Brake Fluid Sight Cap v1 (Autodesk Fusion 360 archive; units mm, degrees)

design "Brake Fluid Sight Cap" references "M4 Mitee Bite", "OP2", "Broached Hexagon Socket Head Cap Screw ANSI B18.3.1M - M4x0.7 x 6 Steel Grade 2 Plain", "Plain Washer ANSI B18.22M - 4 N Steel 100 HV Plain", "Broached Hexagon Socket Head Cap Screw ANSI B18.3.1M - M5x0.8 x 20 Steel Grade 2 Plain", "T-Slot Fence", "Coast Runner CR-1"
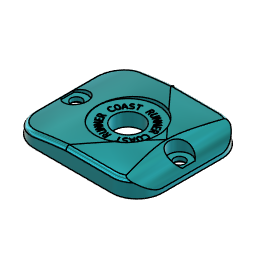
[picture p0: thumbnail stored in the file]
sketch "Sketch1" plane through (0, 0, 0) normal (0, 1, 0) x axis (1, 0, 0)
  line L1 (-22.86, 0) -> (-7.112, 0)
  line L2 (22.86, 0) -> (7.112, 0)
  line L3 (-19.05, 27.305) -> (19.05, 27.305)
  line L4 (-31.75, -14.605) -> (-31.75, 14.605)
  line L5 (19.05, -27.305) -> (-19.05, -27.305)
  line L6 (31.75, 14.605) -> (31.75, -14.605)
  line L7 (-31.75, -27.305) -> (31.75, 27.305)
  line L8 (31.75, -27.305) -> (-31.75, 27.305)
  circle C1 centre (0, 0) radius 7.112
  circle C2 centre (-25.527, 0) radius 2.667
  circle C3 centre (25.527, 0) radius 2.667
  arc A1 centre (19.05, 14.605) radius 12.7 clockwise from (19.05, 27.305) to (31.75, 14.605)
  arc A2 centre (19.05, -14.605) radius 12.7 clockwise from (31.75, -14.605) to (19.05, -27.305)
  arc A3 centre (-19.05, 14.605) radius 12.7 clockwise from (-31.75, 14.605) to (-19.05, 27.305)
  arc A4 centre (-19.05, -14.605) radius 12.7 clockwise from (-19.05, -27.305) to (-31.75, -14.605)
  point P1 (0, 0)
  point P2 (0, 0)
  point P3 (-7.112, 0)
  point P4 (-22.86, 0)
  point P6 (7.112, 0)
  point P7 (22.86, 0)
  point P13 (0, 0)
  point P9 (31.75, 27.305)
  point P12 (31.75, -27.305)
  point P10 (-31.75, 27.305)
  point P11 (-31.75, -27.305)
  coincident P1 P2
  coincident C1 P3
  horizontal L1
  coincident P4 C2
  coincident C1 P6
  horizontal L2
  coincident P7 C3
  horizontal L3
  perpendicular L3 L4
  parallel L3 L5
  parallel L4 L6
  coincident L7 P13
  coincident L8 P13
  coincident P2 P13
  coincident P9 L3
  coincident P9 L6
  tangent L3 A1
  tangent L6 A1
  coincident P12 L6
  coincident P12 L5
  tangent L6 A2
  tangent L5 A2
  coincident P10 L3
  coincident P10 L4
  tangent L3 A3
  tangent L4 A3
  coincident P11 L4
  coincident P11 L5
  tangent L4 A4
  tangent L5 A4
  dimension "d1" diameter C1 = 14.224
  dimension "d2" distance P3 P4 = 15.748
  dimension "d3" diameter C2 = 5.334
  dimension "d4" distance P6 P7 = 15.748
  dimension "d5" diameter C3 = 5.334
  dimension "d6" distance P11 P12 = 63.5
  dimension "d7" distance P10 P11 = 54.61
  dimension "d8" radius A1 = 12.7
  dimension "d9" radius A2 = 12.7
  dimension "d10" radius A3 = 12.7
  dimension "d11" radius A4 = 12.7
work_plane "WorkPlane1" sketch "Sketch1" AlongDistance 9.144
sketch "Sketch2" plane through (0, 9.144, 0) normal (0, 1, 0) x axis (1, 0, 0)
  line L1 (-31.75, -14.605) -> (-31.75, 14.605)
  line L2 (-19.05, 27.305) -> (19.05, 27.305)
  line L3 (31.75, 14.605) -> (31.75, -14.605)
  line L4 (19.05, -27.305) -> (-19.05, -27.305)
  line L5 (19.05, -26.67) -> (-19.05, -26.67)
  line L6 (31.115, 14.605) -> (31.115, -14.605)
  line L7 (-19.05, 26.67) -> (19.05, 26.67)
  line L8 (-31.115, -14.605) -> (-31.115, 14.605)
  line L9 (29.972, 0) -> (28.194, 0)
  line L10 (-29.972, 0) -> (-28.194, 0)
  line L11 (-29.972, 3.1725) -> (-29.972, 0)
  line L12 (-29.972, -3.1725) -> (-29.972, 0)
  line L13 (29.972, 3.1725) -> (29.972, 0)
  line L14 (29.972, -3.1725) -> (29.972, 0)
  arc A1 centre (-19.05, 14.605) radius 12.7 clockwise from (-31.75, 14.605) to (-19.05, 27.305)
  arc A2 centre (19.05, 14.605) radius 12.7 clockwise from (19.05, 27.305) to (31.75, 14.605)
  arc A3 centre (19.05, -14.605) radius 12.7 clockwise from (31.75, -14.605) to (19.05, -27.305)
  arc A4 centre (-19.05, -14.605) radius 12.7 clockwise from (-19.05, -27.305) to (-31.75, -14.605)
  arc A5 centre (-19.05, -14.605) radius 12.065 clockwise from (-19.05, -26.67) to (-31.115, -14.605)
  arc A6 centre (19.05, -14.605) radius 12.065 clockwise from (31.115, -14.605) to (19.05, -26.67)
  arc A7 centre (19.05, 14.605) radius 12.065 clockwise from (19.05, 26.67) to (31.115, 14.605)
  arc A8 centre (-19.05, 14.605) radius 12.065 clockwise from (-31.115, 14.605) to (-19.05, 26.67)
  circle C1 centre (-25.527, 0) radius 2.667
  circle C2 centre (0, 0) radius 7.112
  circle C3 centre (25.527, 0) radius 2.667
  circle C4 centre (-25.527, 0) radius 5.461
  circle C5 centre (25.527, 0) radius 5.461
  circle C6 centre (0, 0) radius 14.986
  point P29 (28.194, 0)
  point P31 (-28.194, 0)
  point P35 (-29.972, 3.1725)
  point P36 (-29.972, -3.1725)
  point P37 (29.972, 3.1725)
  point P38 (29.972, -3.1725)
  point P30 (29.972, 0)
  point P32 (-29.972, 0)
  coincident C3 P29
  perpendicular L6 L9
  coincident C1 P31
  horizontal L10
  concentric C1 C4
  concentric C3 C5
  coincident C4 P35
  perpendicular L10 L11
  coincident C4 P36
  perpendicular L10 L12
  coincident C5 P37
  perpendicular L9 L13
  coincident C5 P38
  perpendicular L9 L14
  concentric C2 C6
  dimension "d13" = -0.635
  dimension "d42" distance P29 P30 = 1.778
  dimension "d43" distance P31 P32 = 1.778
  dimension "d44" diameter C4 = 10.922
  dimension "d45" diameter C5 = 10.922
  dimension "d46" diameter C6 = 29.972
loft "Loft1" sketch "Sketch1" + "Sketch2"
sketch "Sketch3" plane through (0, 0, 0) normal (1, 0, 0) x axis (0, 0, -1)
  line L1 (26.67, 9.144) -> (-26.67, 9.144)
  line L2 (27.305, 0) -> (-27.305, 0)
  line L3 (0, 9.144) -> (0, 0)
  line L4 (0, 7.874) -> (0, 9.144)
  line L5 (-28.702, 7.874) -> (0, 7.874)
  line L6 (-26.67, 9.144) -> (-27.178, 7.874)
  line L7 (0, 9.144) -> (0, 7.874)
  line L8 (26.67, 9.144) -> (27.178, 7.874)
  arc A1 centre (0, -282.2956) radius 291.4396 clockwise from (-27.178, 7.874) to (0, 9.144)
  arc A2 centre (0, -282.2956) radius 291.4396 clockwise from (0, 9.144) to (27.178, 7.874)
  point P1 (0, 0)
  point P6 (0, 0)
  point P7 (0, 9.144)
  point P8 (0, 7.874)
  point P10 (-27.178, 7.874)
  point P2 (-26.67, 9.144)
  point P12 (-26.67, 9.144)
  point P16 (0, 9.144)
  point P13 (27.178, 7.874)
  point P14 (26.67, 9.144)
  coincident P1 P6
  midpoint L1 P7
  coincident L3 P8
  perpendicular L4 L5
  tangent L1 A1
  coincident L5 P10
  coincident P2 P12
  symmetric P7 L3 P16
  symmetric L3 P10 P13
  symmetric L3 A1 A2
  symmetric L3 P12 P14
  dimension "d14" distance P7 P8 = 1.27
sketch "Sketch4" plane through (0, 0, 0) normal (0, 0, 1) x axis (1, 0, 0)
  line L1 (-31.75, 3.81) -> (-31.75, 0)
  line L2 (41.4602, 3.81) -> (-31.75, 3.81)
  line L3 (19.05, 3.81) -> (-31.75, 3.81)
  line L4 (31.115, 9.144) -> (-31.115, 9.144)
  line L5 (19.05, 9.144) -> (19.05, 3.81)
  line L6 (-31.75, 3.81) -> (-31.115, 9.144)
  line L7 (19.05, 9.144) -> (-31.115, 9.144)
  line L8 (31.75, 1.778) -> (31.75, 0)
  line L9 (31.115, 9.144) -> (31.75, 1.778)
  line L10 (19.05, 9.144) -> (31.115, 9.144)
  arc A1 centre (19.05, -235.4278) radius 244.5718 clockwise from (-31.75, 3.81) to (19.05, 9.144)
  arc A2 centre (17.1186, -8.8173) radius 18.0649 clockwise from (19.05, 9.144) to (31.75, 1.778)
  point P5 (19.05, 3.81)
  point P8 (19.05, 9.144)
  point P6 (-31.115, 9.144)
  point P10 (-31.115, 9.144)
  point P7 (31.115, 9.144)
  point P14 (31.115, 9.144)
  point P15 (31.115, 9.144)
  point P2 (-31.75, 0)
  point P3 (-31.75, 3.81)
  point P11 (31.75, 0)
  point P12 (31.75, 1.778)
  vertical L1
  perpendicular L1 L2
  coincident L2 P5
  coincident L4 P8
  perpendicular L4 L5
  tangent L4 A1
  coincident P6 P10
  vertical L8
  coincident P7 P14
  coincident P7 P15
  dimension "d15" distance P2 P3 = 3.81
  dimension "d16" distance P3 P5 = 50.8
  dimension "d17" distance P11 P12 = 1.778
extrude "Extrude1" cut sketch "Sketch4" profile of A1 L6 L7 A2 L9 L10 distance 58.42
extrude "Extrude2" cut sketch "Sketch3" profile of L1 A1 L6 L8 A2 distance 52.07
extrude "Extrude3" cut sketch "Sketch1" profile of C1 C2 C3 along normal blind 39.37
sketch "Sketch5" plane through (0, 0, 0) normal (0, -1, 0) x axis (1, 0, 0)
  curve K1 (-31.75, 14.605) -> (-31.75, 14.605)
  curve K2 (-31.75, 14.605) -> (-31.75, 14.605)
  circle C1 centre (-25.527, 0) radius 2.667
  circle C2 centre (0, 0) radius 7.112
  circle C3 centre (25.527, 0) radius 2.667
  circle C4 centre (25.527, 0) radius 6.35
  circle C5 centre (-25.527, 0) radius 6.35
  circle C6 centre (0, 0) radius 9.779
  concentric C3 C4
  concentric C1 C5
  concentric C2 C6
  dimension "d24" = 3.556
  dimension "d25" diameter C4 = 12.7
  dimension "d26" diameter C5 = 12.7
  dimension "d27" diameter C6 = 19.558
extrude "Extrude4" cut sketch "Sketch5" profile of C4 C5 C6 against normal blind 3.556
fillet "Fillet1" radius 1.905
sketch "Sketch6" plane through (0, 0, 0) normal (0, -1, 0) x axis (1, 0, 0)
  curve K1 (-31.75, 14.605) -> (-31.75, 14.605)
  curve K2 (-28.194, -5.7628) -> (28.194, -5.7628)
  line L1 (-28.194, 14.605) -> (-28.194, 5.7628)
  curve K3 (28.194, 5.7628) -> (-28.194, 14.605)
  line L2 (-31.75, -27.2198) -> (-31.75, 0)
  line L3 (-15.2401, -23.749) -> (-31.75, -23.6999)
  line L4 (-13.4621, -23.749) -> (-15.2401, -23.749)
  line L5 (-13.4621, -28.9225) -> (-13.4621, -23.749)
  line L6 (-15.2401, -28.9225) -> (-13.4621, -28.9225)
  line L7 (-15.2401, -23.749) -> (-15.2401, -28.9225)
  line L8 (31.75, 36.9995) -> (31.75, -0.077)
  line L9 (31.75, 27.305) -> (15.24, 27.305)
  line L10 (13.462, 27.305) -> (15.24, 27.305)
  line L11 (13.462, 22.4524) -> (13.462, 27.305)
  line L12 (15.24, 22.4524) -> (13.462, 22.4524)
  line L13 (15.24, 27.305) -> (15.24, 22.4524)
  circle C1 centre (25.527, 0) radius 2.667
  circle C2 centre (-25.527, 0) radius 2.667
  arc A1 centre (25.527, 0) radius 6.35 clockwise from (28.194, -5.7628) to (28.194, 5.7628)
  arc A2 centre (-25.527, 0) radius 6.35 clockwise from (-28.194, 5.7628) to (-28.194, -5.7628)
  circle C3 centre (-25.527, 0) radius 4.064
  circle C4 centre (25.527, 0) radius 4.064
  point P13 (-31.75, 0)
  point P15 (-31.75, -23.6999)
  point P16 (-15.2401, -23.749)
  point P20 (31.75, -0.077)
  point P22 (15.24, 27.305)
  point P23 (31.75, 27.305)
  point P17 (-13.4621, -23.749)
  point P24 (13.462, 27.305)
  concentric C2 C3
  concentric C1 C4
  coincident K1 P13
  vertical L2
  coincident L2 P15
  coincident K2 P16
  horizontal L4
  vertical L5
  horizontal L6
  vertical L7
  coincident K1 P20
  vertical L8
  coincident K1 P22
  coincident L8 P23
  perpendicular L8 L9
  horizontal L10
  vertical L11
  horizontal L12
  vertical L13
  dimension "d32" diameter C3 = 8.128
  dimension "d33" diameter C4 = 8.128
  dimension "d34" distance P15 P16 = 16.51
  dimension "d35" distance P16 P17 = 1.778
  dimension "d36" distance P22 P23 = 16.51
  dimension "d37" distance P22 P24 = 1.778
extrude "Extrude5" cut sketch "Sketch6" profile of K1 K2 K3 L4 L5 L7 L10 L11 L13 against normal blind 0.762
extrude "Extrude6" cut sketch "Sketch6" profile of C1 C2 C3 C4 against normal blind 1.27
extrude "Extrude7" cut sketch "Sketch2" profile of C2 C6 against normal blind 2.54
fillet "Fillet2" radius 0.635
extrude "Extrude8" cut sketch "Sketch2" profile of C1 C3 C4 C5 L11 L12 L13 L14 against normal blind 5.842
fillet "Fillet3" radius 0.508
chamfer "Chamfer1" distance 1.27
sketch "Sketch1" plane through (0, 0, 0) normal (0, -1, 0) x axis (1, 0, 0)
  line L1 (-34.925, 28.575) -> (34.925, 28.575)
  line L2 (-34.925, -28.575) -> (-34.925, 28.575)
  line L3 (34.925, -28.575) -> (-34.925, -28.575)
  line L4 (34.925, 28.575) -> (34.925, -28.575)
  line L5 (-34.925, -28.575) -> (34.925, 28.575)
  line L6 (34.925, -28.575) -> (-34.925, 28.575)
  circle C1 centre (0, 0) radius 9.779
  circle C2 centre (0, 0) radius 7.112
  point P7 (0, 0)
  point P2 (0, 0)
  point P5 (-34.925, -28.575)
  point P6 (34.925, -28.575)
  point P4 (-34.925, 28.575)
  horizontal L1
  perpendicular L1 L2
  parallel L1 L3
  parallel L2 L4
  coincident L5 P7
  coincident L6 P7
  coincident P2 P7
  dimension "d56" distance P5 P6 = 69.85
  dimension "d57" distance P4 P5 = 57.15
extrude "Extrude1" new body sketch "Sketch1" profile of C1 C2 L1 L2 L3 L4 against normal blind 12.7
base_feature "Base Feature1"
copy_paste "CutPaste2"
component_from_bodies "Body->Comp"
base_feature "Base Feature1"
delete_face "DeleteFace1"
delete_face "DeleteFace2"
delete_face "DeleteFace3"
delete_face "DeleteFace4"
sketch "Sketch7" plane through (0, 3.556, 0) normal (0, -1, 0) x axis (1, 0, 0)
  curve K1 (-28.194, -5.7628) -> (28.194, -5.7628)
  curve K2 (28.194, 5.7628) -> (-28.194, 14.605)
  line L1 (-28.194, 14.605) -> (-28.194, 5.7628)
  curve K3 (28.194, 5.7628) -> (15.24, 23.749)
  line L2 (-28.194, 14.605) -> (-28.194, 5.7628)
  curve K4 (-28.194, -5.7628) -> (-15.2401, -23.749)
  curve K5 (-13.4621, -23.749) -> (28.194, -5.7628)
  line L3 (25.527, 0) -> (-25.527, 0)
  line L4 (0, 23.749) -> (0, 0)
  circle C1 centre (0, 0) radius 9.779
  arc A1 centre (25.527, 0) radius 6.35 clockwise from (28.194, -5.7628) to (28.194, 5.7628)
  arc A2 centre (-25.527, 0) radius 6.35 clockwise from (-28.194, 5.7628) to (-28.194, -5.7628)
  arc A3 centre (-25.527, 0) radius 6.35 clockwise from (-28.194, 5.7628) to (-28.194, -5.7628)
  arc A4 centre (25.527, 0) radius 6.35 clockwise from (28.194, -5.7628) to (28.194, 5.7628)
  arc A5 centre (-24.384, 10.0955) radius 3.81 clockwise from (-24.8126, 6.3097) to (-28.194, 10.0955)
  arc A6 centre (24.384, 10.0955) radius 3.81 clockwise from (28.194, 10.0955) to (24.8126, 6.3097)
  arc A7 centre (24.384, -10.0955) radius 3.81 clockwise from (24.8126, -6.3097) to (28.194, -10.0955)
  arc A8 centre (-24.384, -10.0955) radius 3.81 clockwise from (-28.194, -10.0955) to (-24.8126, -6.3097)
  point P21 (-24.8126, 6.3097)
  point P22 (-28.194, 10.0955)
  point P16 (-25.527, 0)
  point P23 (-25.527, 0)
  point P20 (25.527, 0)
  point P24 (25.527, 0)
  point P2 (0, 0)
  point P25 (0, 0)
  point P26 (0, 23.749)
  point P29 (24.8126, 6.3097)
  point P28 (28.194, 10.0955)
  point P35 (-24.8126, -6.3097)
  point P34 (-28.194, -10.0955)
  point P32 (28.194, -10.0955)
  point P31 (24.8126, -6.3097)
  tangent A2 A5
  tangent L2 A5
  coincident A2 P21
  coincident L1 P22
  coincident P16 P23
  coincident P20 P24
  coincident P2 P25
  coincident K2 P26
  perpendicular L3 L4
  symmetric P21 L4 P29
  symmetric P22 L4 P28
  symmetric A5 L4 A6
  symmetric P21 L3 P35
  symmetric P22 L3 P34
  symmetric A5 L3 A8
  symmetric L3 P28 P32
  symmetric L3 P29 P31
  symmetric L3 A6 A7
  dimension "d60" diameter A5 = 7.62
extrude "Extrude1" add sketch "Sketch7" profile of K1 A1 K2 L1 A2 A5 K3 L2 A3 K4 K5 A4 A6 A7 A8 along normal blind 3.556
sketch "Sketch9" plane through (0, 6.604, 0) normal (0, 1, 0) x axis (-1, 0, 0)
  curve K1 (10.914, 10.2696) -> (10.914, -10.2696)
  circle C1 centre (0, 0) radius 7.112
  arc A1 centre (0, 0) radius 14.986 clockwise from (10.914, -10.2696) to (10.914, 10.2696)
  circle C2 centre (0, 0) radius 8.89
  point P1 (0, 0)
  point P5 (0, 0)
  coincident P1 P5
  dimension "d69" diameter C2 = 17.78
  dimension "d64" Text1-Height = 2.9845
emboss "Emboss1" sketch "Sketch9" Depth -0.254 Horizontal Distance 0 Vertical Distance 0 Rotation Angle 0
sketch "Profile" plane through (0, 0, 0) normal (0, -1, 0) x axis (1, 0, 0)
  line L1 (13.462, 27.305) -> (13.462, 23.749)
  curve K1 (13.462, 27.305) -> (-31.75, 14.605)
  curve K2 (-31.75, 14.605) -> (-15.2401, -27.305)
  line L2 (-15.2401, -23.749) -> (-15.2401, -27.305)
  curve K3 (-28.194, -10.0955) -> (-15.2401, -23.749)
  line L3 (-28.194, 14.605) -> (-28.194, 10.0955)
  curve K4 (13.462, 23.749) -> (-28.194, 14.605)
  curve K5 (13.462, 27.305) -> (-31.75, 14.605)
  line L4 (15.24, 27.2521) -> (13.462, 27.2521)
  curve K6 (-13.4621, -27.305) -> (15.24, 27.305)
  line L5 (-15.2401, -27.2521) -> (-13.4621, -27.2521)
  curve K7 (-31.75, 14.605) -> (-15.2401, -27.305)
  curve K8 (-40.64, 14.605) -> (-15.2401, -36.195)
  curve K9 (18.4701, 36.195) -> (-40.64, 14.605)
  curve K10 (-15.2401, -36.195) -> (15.24, 36.195)
  line L6 (-13.4621, -27.305) -> (-15.2401, -27.305)
  line L7 (15.24, 27.305) -> (13.462, 27.305)
  line L8 (60.228, 47.2634) -> (-60.228, 47.2634)
  line L9 (60.228, -47.2634) -> (60.228, 47.2634)
  line L10 (-60.228, -47.2634) -> (60.228, -47.2634)
  line L11 (-60.228, 47.2634) -> (-60.228, -47.2634)
  line L12 (60.228, -47.2634) -> (-60.228, 47.2634)
  line L13 (-60.228, -47.2634) -> (60.228, 47.2634)
  circle C1 centre (-25.527, 0) radius 4.064
  arc A1 centre (-24.384, -10.0955) radius 3.81 clockwise from (-28.194, -10.0955) to (-24.8126, -6.3097)
  arc A2 centre (-25.527, 0) radius 6.35 clockwise from (-24.8126, 6.3097) to (-24.8126, -6.3097)
  arc A3 centre (-24.384, 10.0955) radius 3.81 clockwise from (-24.8126, 6.3097) to (-28.194, 10.0955)
  point P27 (18.4701, 36.195)
  point P23 (-15.2401, -27.305)
  point P28 (-15.2401, -27.305)
  point P20 (-13.4621, -27.305)
  point P29 (-13.4621, -27.305)
  point P16 (13.462, 27.305)
  point P30 (13.462, 27.305)
  point P19 (15.24, 27.305)
  point P31 (15.24, 27.305)
  point P36 (0, 0)
  point P1 (0, 0)
  coincident P27 K10
  coincident P23 P28
  coincident P20 P29
  coincident P16 P30
  coincident P19 P31
  horizontal L8
  perpendicular L8 L9
  parallel L8 L10
  parallel L9 L11
  coincident L12 P36
  coincident L13 P36
  coincident P1 P36
delete_face "DeleteFace5"
delete_face "DeleteFace6"
delete_face "DeleteFace7"
delete_face "DeleteFace8"
delete_face "DeleteFace9"
delete_face "DeleteFace10"
extrude "Extrude2" cut of existing geometry blind -3.048
extrude "Extrude3" cut of existing geometry blind -0.254
component_insert "Component Insert5"
component_insert "Component Insert6"
copy_paste "CutPaste1"
copy_paste "CutPaste2"
component_insert "Component Insert7"
position "Position2"
copy_paste "CutPaste3"
step "Washer1" sketch "Sketch6"
joint "Assemble1" sketch "Sketch6" alignAngle 0 alignOffsetX 1.6256 alignOffsetY 0.0762 alignOffsetZ 0
joint "Assemble2" alignAngle 0 alignOffsetX 0 alignOffsetY 0 alignOffsetZ -8.636
step "Washer2" sketch "Sketch6"
joint "Assemble3" sketch "Sketch6" alignAngle 0 alignOffsetX 1.6256 alignOffsetY 0.0762 alignOffsetZ 0
joint "Assemble4" alignAngle 0 alignOffsetX 0 alignOffsetY 0 alignOffsetZ -8.636
step "Washer3" sketch "Sketch6"
joint "Assemble5" sketch "Sketch6" alignAngle 0 alignOffsetX 1.6256 alignOffsetY 0.0762 alignOffsetZ 0
joint "Assemble6" alignAngle 0 alignOffsetX 0 alignOffsetY 0 alignOffsetZ -8.636
step "Screw4"
joint "Assemble7" alignAngle 0 alignOffsetX 0 alignOffsetY 0 alignOffsetZ 0
step "Screw5"
joint "Assemble8" alignAngle 0 alignOffsetX 0 alignOffsetY 0 alignOffsetZ 0
step "Screw6"
joint "Assemble9" alignAngle 0 alignOffsetX 0 alignOffsetY 0 alignOffsetZ 0
component_insert "Component Insert1"
base_feature "Base Feature1"
position "Position3"
copy_paste_bodies "CopyPasteBodies1"
step "Screw1"
joint "Assemble1" alignAngle 0 alignOffsetX 0 alignOffsetY 0 alignOffsetZ 0
step "Screw2"
joint "Assemble2" alignAngle 0 alignOffsetX 0 alignOffsetY 0 alignOffsetZ 0
copy_paste "CutPaste1"
copy_paste "CutPaste2"
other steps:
base_feature "Base Feature1"
base_feature "Base Feature2" bodies "Part Location"
create_component "CreateComponent1"
create_component "CreateComponent3"
create_component "CreateComponent4"
remove_instance "RemoveInstance2"
create_component "CreateComponent5"
remove_body "RemoveBody1"
create_component "CreateComponent6"
remove_instance "RemoveInstance3"
remove_instance "RemoveInstance4"
remove_instance "RemoveInstance5"
joint_origin "JointOrigin4"
joint_origin "JointOrigin5"
joint_origin "JointOrigin6"
create_component "CreateComponent1"
joint_origin "JointOrigin1"
joint_origin "JointOrigin2"
create_component "CreateComponent7"
remove_instance "RemoveInstance6"
remove_instance "RemoveInstance7"
named bodies: "Part Location"

design "T-Slot Fence"
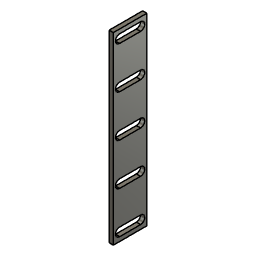
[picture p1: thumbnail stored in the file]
derived_context "DerivedContext1"
sketch "Sketch3" plane through (-250.5206, 0, 0) normal (1, 0, 0) x axis (0, 1, 0)
  line L1 (-76.85, 14.605) -> (-261.0089, 14.605)
  line L2 (-76.85, 103.505) -> (-76.85, 14.605)
  line L3 (-261.0089, 103.505) -> (-76.85, 103.505)
  line L4 (-261.0089, 14.605) -> (-261.0089, 103.505)
  line L5 (-166.3954, 33.655) -> (-166.3954, 20.955)
  line L6 (-171.4754, 20.955) -> (-171.4754, 33.655)
  line L7 (-168.9354, 33.655) -> (-168.9354, 20.955)
  line L8 (-224.8154, 37.465) -> (-113.0554, 37.465)
  line L9 (-224.8154, 17.145) -> (-224.8154, 37.465)
  line L10 (-113.0554, 17.145) -> (-224.8154, 17.145)
  line L11 (-113.0554, 37.465) -> (-113.0554, 17.145)
  line L12 (-224.8154, 17.145) -> (-113.0554, 37.465)
  line L13 (-113.0554, 17.145) -> (-224.8154, 37.465)
  circle C1 centre (-181.6405, 17.7778) radius 1.4986
  circle C2 centre (-181.6405, 100.3278) radius 1.4986
  circle C3 centre (-207.0405, 17.7778) radius 1.4986
  circle C4 centre (-207.0405, 100.3278) radius 1.4986
  circle C5 centre (-232.4405, 17.7778) radius 1.4986
  circle C6 centre (-232.4405, 100.3278) radius 1.4986
  circle C7 centre (-257.8354, 97.155) radius 2.286
  circle C8 centre (-257.8354, 20.955) radius 2.286
  circle C9 centre (-80.0354, 97.155) radius 2.286
  circle C10 centre (-80.0354, 20.955) radius 2.286
  circle C11 centre (-156.2405, 100.3278) radius 1.4986
  circle C12 centre (-156.2405, 17.7778) radius 1.4986
  circle C13 centre (-130.8405, 100.3278) radius 1.4986
  circle C14 centre (-130.8405, 17.7778) radius 1.4986
  circle C15 centre (-105.4405, 100.3278) radius 1.4986
  circle C16 centre (-105.4405, 17.7778) radius 1.4986
  circle C17 centre (-105.4354, 33.655) radius 2.286
  circle C18 centre (-105.4354, 59.055) radius 2.286
  circle C19 centre (-105.4354, 84.455) radius 2.286
  circle C20 centre (-118.1354, 97.155) radius 2.286
  circle C21 centre (-118.1354, 71.755) radius 2.286
  circle C22 centre (-118.1354, 46.355) radius 2.286
  circle C23 centre (-118.1354, 20.955) radius 2.286
  circle C24 centre (-130.8354, 33.655) radius 2.286
  circle C25 centre (-130.8354, 59.055) radius 2.286
  circle C26 centre (-130.8354, 84.455) radius 2.286
  circle C27 centre (-143.5354, 97.155) radius 2.286
  circle C28 centre (-143.5354, 71.755) radius 2.286
  circle C29 centre (-143.5354, 46.355) radius 2.286
  circle C30 centre (-143.5354, 20.955) radius 2.286
  circle C31 centre (-156.2354, 33.655) radius 2.286
  circle C32 centre (-156.2354, 59.055) radius 2.286
  circle C33 centre (-156.2354, 84.455) radius 2.286
  circle C34 centre (-168.9354, 97.155) radius 2.286
  circle C35 centre (-168.9354, 71.755) radius 2.286
  circle C36 centre (-168.9354, 33.655) radius 2.286
  circle C37 centre (-181.6354, 46.355) radius 2.286
  circle C38 centre (-181.6354, 71.755) radius 2.286
  circle C39 centre (-194.3354, 84.455) radius 2.286
  circle C40 centre (-194.3354, 59.055) radius 2.286
  circle C41 centre (-194.3354, 33.655) radius 2.286
  circle C42 centre (-207.0354, 46.355) radius 2.286
  circle C43 centre (-207.0354, 71.755) radius 2.286
  circle C44 centre (-219.7354, 84.455) radius 2.286
  circle C45 centre (-219.7354, 59.055) radius 2.286
  circle C46 centre (-219.7354, 33.655) radius 2.286
  circle C47 centre (-232.4354, 46.355) radius 2.286
  circle C48 centre (-232.4354, 71.755) radius 2.286
  circle C49 centre (-245.1354, 84.455) radius 2.286
  circle C50 centre (-245.1354, 59.055) radius 2.286
  circle C51 centre (-245.1354, 33.655) radius 2.286
  circle C52 centre (-257.8354, 71.755) radius 2.286
  circle C53 centre (-257.8354, 46.355) radius 2.286
  circle C54 centre (-92.7354, 84.455) radius 2.286
  circle C55 centre (-92.7354, 59.055) radius 2.286
  circle C56 centre (-92.7354, 33.655) radius 2.286
  circle C57 centre (-80.0354, 71.755) radius 2.286
  circle C58 centre (-80.0354, 46.355) radius 2.286
  circle C59 centre (-80.0354, 33.655) radius 2.286
  circle C60 centre (-80.0354, 59.055) radius 2.286
  circle C61 centre (-80.0354, 84.455) radius 2.286
  circle C62 centre (-92.7354, 20.955) radius 2.286
  circle C63 centre (-92.7354, 46.355) radius 2.286
  circle C64 centre (-92.7354, 71.755) radius 2.286
  circle C65 centre (-92.7354, 97.155) radius 2.286
  circle C66 centre (-257.8354, 33.655) radius 2.286
  circle C67 centre (-257.8354, 59.055) radius 2.286
  circle C68 centre (-257.8354, 84.455) radius 2.286
  circle C69 centre (-245.1354, 20.955) radius 2.286
  circle C70 centre (-245.1354, 46.355) radius 2.286
  circle C71 centre (-245.1354, 71.755) radius 2.286
  circle C72 centre (-245.1354, 97.155) radius 2.286
  circle C73 centre (-232.4354, 84.455) radius 2.286
  circle C74 centre (-232.4354, 59.055) radius 2.286
  circle C75 centre (-232.4354, 33.655) radius 2.286
  circle C76 centre (-219.7354, 20.955) radius 2.286
  circle C77 centre (-219.7354, 46.355) radius 2.286
  circle C78 centre (-219.7354, 71.755) radius 2.286
  circle C79 centre (-219.7354, 97.155) radius 2.286
  circle C80 centre (-207.0354, 84.455) radius 2.286
  circle C81 centre (-207.0354, 59.055) radius 2.286
  circle C82 centre (-207.0354, 33.655) radius 2.286
  circle C83 centre (-194.3354, 20.955) radius 2.286
  circle C84 centre (-194.3354, 46.355) radius 2.286
  circle C85 centre (-194.3354, 71.755) radius 2.286
  circle C86 centre (-194.3354, 97.155) radius 2.286
  circle C87 centre (-181.6354, 84.455) radius 2.286
  circle C88 centre (-181.6354, 59.055) radius 2.286
  circle C89 centre (-181.6354, 33.655) radius 2.286
  circle C90 centre (-168.9354, 20.955) radius 2.286
  circle C91 centre (-168.9354, 46.355) radius 2.286
  circle C92 centre (-168.9354, 84.455) radius 2.286
  circle C93 centre (-156.2354, 71.755) radius 2.286
  circle C94 centre (-156.2354, 46.355) radius 2.286
  circle C95 centre (-143.5354, 33.655) radius 2.286
  circle C96 centre (-143.5354, 59.055) radius 2.286
  circle C97 centre (-143.5354, 84.455) radius 2.286
  circle C98 centre (-130.8354, 71.755) radius 2.286
  circle C99 centre (-130.8354, 46.355) radius 2.286
  circle C100 centre (-118.1354, 33.655) radius 2.286
  circle C101 centre (-118.1354, 59.055) radius 2.286
  circle C102 centre (-118.1354, 84.455) radius 2.286
  circle C103 centre (-105.4354, 71.755) radius 2.286
  circle C104 centre (-105.4354, 46.355) radius 2.286
  circle C105 centre (-86.3854, 40.005) radius 1.4986
  circle C106 centre (-86.3854, 65.405) radius 1.4986
  circle C107 centre (-86.3854, 90.805) radius 1.4986
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  point P41 (-168.9354, 33.655)
  point P214 (-168.9354, 33.655)
  point P199 (-168.9354, 20.955)
  point P213 (-168.9354, 20.955)
  point P219 (-168.9354, 27.305)
  point P217 (-224.8154, 17.145)
  point P218 (-113.0554, 17.145)
  point P216 (-224.8154, 37.465)
  parallel L5 L6
  coincident P41 P214
  vertical L7
  coincident P199 P213
  horizontal L8
  perpendicular L8 L9
  parallel L8 L10
  parallel L9 L11
  coincident L12 P219
  coincident L13 P219
  midpoint L7 P219
  dimension "d1" distance P217 P218 = 111.76
  dimension "d2" distance P216 P217 = 20.32
  dimension "d10" distance L5 L6 = 5.08
extrude "Extrude1" new body sketch "Sketch3" along normal blind 2.54
rectangular_pattern "R-Pattern1" uSpaceDistance 50.8 vSpaceDistance 0
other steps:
derived_base_feature "Derived Base Feature" bodies "Body1"
named bodies: "Body1"

design "M4 mitee bite" references "bolt", "hex"
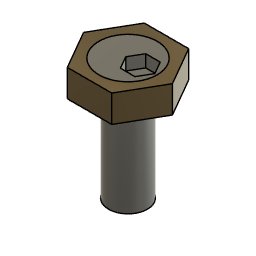
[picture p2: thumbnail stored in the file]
component_insert "Component Insert1"
component_insert "Component Insert2"
step "Context"

design "M4 Mitee Bite" references "M4 mitee bite"
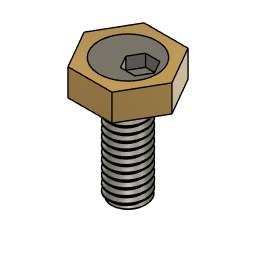
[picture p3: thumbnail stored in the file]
external_derived "ExternalDerived1" bodies "Eccentric M4 Screw", "M4 Clamp Nut"
thread "Thread1"
chamfer "Chamfer1" distance 0.254
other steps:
derived_base_feature "Derived Base Feature1" bodies "Eccentric M4 Screw"
derived_base_feature "Derived Base Feature2" bodies "M4 Clamp Nut"
named bodies: "Eccentric M4 Screw", "M4 Clamp Nut"

design "Coast Runner CR-1"
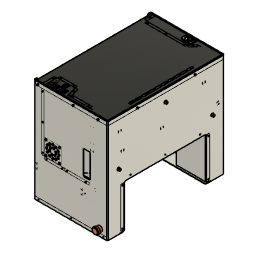
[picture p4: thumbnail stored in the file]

design "hex"
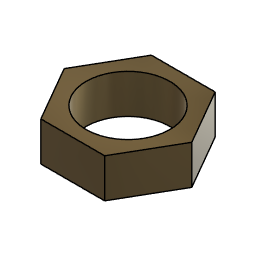
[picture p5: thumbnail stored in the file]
derived_context "DerivedContext1"
sketch "Sketch1" plane through (0, 12.5, 0) normal (0, 1, 0) x axis (-1, 0, 0)
  line L1 (-4.5784, 0) -> (-2.2892, 3.965)
  line L2 (-2.2892, -3.965) -> (-4.5784, 0)
  line L3 (2.2892, -3.965) -> (-2.2892, -3.965)
  line L4 (4.5784, 0) -> (2.2892, -3.965)
  line L5 (2.2892, 3.965) -> (4.5784, 0)
  line L6 (-2.2892, 3.965) -> (2.2892, 3.965)
  line L7 (-2.0257, -1.2957) -> (-0.5258, -1.3023)
  line L8 (-2.77, 0.0066) -> (-2.0257, -1.2957)
  line L9 (-2.0142, 1.3023) -> (-2.77, 0.0066)
  line L10 (-0.5143, 1.2957) -> (-2.0142, 1.3023)
  line L11 (0.23, -0.0066) -> (-0.5143, 1.2957)
  line L12 (-0.5258, -1.3023) -> (0.23, -0.0066)
  circle C1 centre (0, 0) radius 3
  circle C2 centre (0, 0) radius 3
  point P1 (0, 0)
  point P9 (0, 0)
  point P10 (0, 0)
  coincident P1 P9
  coincident P1 P10
  dimension "d1" distance P9 L6 = 3.965
  dimension "d2" diameter C2 = 6
extrude "Extrude1" new body sketch "Sketch1" profile of C1 L1 L2 L3 L4 L5 L6 C2 against normal blind 2.8
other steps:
derived_base_feature "Derived Base Feature" bodies "Body1"
named bodies: "Body1"

design "Plain Washer ANSI B18.22M - 4 N Steel 100 HV Plain"
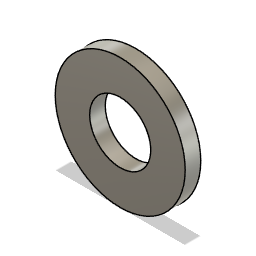
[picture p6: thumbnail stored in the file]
description: Plain Washer ANSI B18.22M - 4 N
part number: arrangementsContainer
parameter "adsk_woutdia" = 10
parameter "adsk_windia" = 4.7
parameter "adsk_wthick" = 1.2
sketch "Sketch1" plane through (0, 0, 0) normal (0, 0, 1) x axis (1, 0, 0)
  circle C1 centre (0, 0) radius 5
  circle C2 centre (0, 0) radius 2.35
  point P1 (0, 0)
  point P2 (0, 0)
  point P3 (0, 0)
  coincident P1 P2
  coincident P1 P3
  dimension "d4" diameter C1 = 10 (= "adsk_woutdia")
  dimension "d5" diameter C2 = 4.7 (= "adsk_windia")
extrude "Extrude1" new body sketch "Sketch1" along normal blind 1.2 (= "adsk_wthick")
joint_origin "JointOrigin4" OffsetX 0 OffsetY 0 OffsetZ 0 AngleZ 0
joint_origin "JointOrigin6" OffsetX 0 OffsetY 0 OffsetZ 1.2 (= "adsk_wthick") AngleZ 0

design "OP2" references "Broached Hexagon Socket Head Cap Screw ANSI B18.3.1M - M4x0.7 x 6 Steel Grade 2 Plain", "Plain Washer ANSI B18.22M - 4 N Steel 100 HV Plain", "T-Slot Fence", "M4 Mitee Bite"
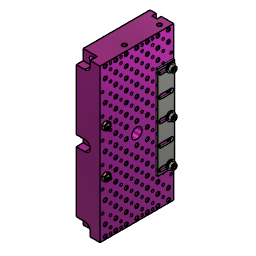
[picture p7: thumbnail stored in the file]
base_feature "Base Feature"
position "Position1"
position "Position2"
component_insert "Component Insert1"
copy_paste "CutPaste"
position "Position3"
position "Position2"
component_insert "Component Insert2"
step "Washer1"
joint "Assemble1" alignAngle 0 alignOffsetX 1.6256 alignOffsetY 0.0762 alignOffsetZ 0
joint "Assemble2" alignAngle 0 alignOffsetX 0 alignOffsetY 0 alignOffsetZ -8.636
step "Washer2"
joint "Assemble3" alignAngle 0 alignOffsetX 1.6256 alignOffsetY 0.0762 alignOffsetZ 0
joint "Assemble4" alignAngle 0 alignOffsetX 0 alignOffsetY 0 alignOffsetZ -8.636
step "Washer3"
joint "Assemble5" alignAngle 0 alignOffsetX 1.6256 alignOffsetY 0.0762 alignOffsetZ 0
joint "Assemble6" alignAngle 0 alignOffsetX 0 alignOffsetY 0 alignOffsetZ -8.636
step "Screw4"
joint "Assemble7" alignAngle 0 alignOffsetX 0 alignOffsetY 0 alignOffsetZ 0
step "Screw5"
joint "Assemble8" alignAngle 0 alignOffsetX 0 alignOffsetY 0 alignOffsetZ 0
step "Screw6"
joint "Assemble9" alignAngle 0 alignOffsetX 0 alignOffsetY 0 alignOffsetZ 0
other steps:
joint_origin "JointOrigin4"
joint_origin "JointOrigin5"
joint_origin "JointOrigin6"

design "Broached Hexagon Socket Head Cap Screw ANSI B18.3.1M - M4x0.7 x 6 Steel Grade 2 Plain"
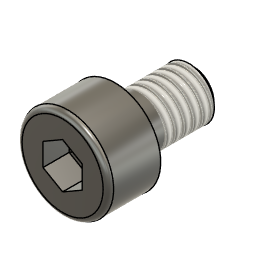
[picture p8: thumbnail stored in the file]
description: Broached Hexagon Socket Head Cap Screw ANSI B18.3.1M - M4x0.7 x 6
part number: arrangementsContainer
parameter "adsk_nomlen" = 6
parameter "adsk_headh" = 4
parameter "adsk_headdia" = 7
parameter "adsk_nomdia" = 4
parameter "adsk_waflat" = 3
parameter "adsk_keyend" = 2
parameter "adsk_thrlen" = 4.1706
parameter "adsk_startlen" = 0.4294
parameter "adsk_endpointdia" = 3.1412
sketch "Sketch1" plane through (0, 0, 0) normal (0, 1, 0) x axis (1, 0, 0)
  line L1 (-2, 6) -> (-2, 0)
  line L2 (0, 6) -> (-2, 6)
  line L3 (0, -4) -> (0, 6)
  line L4 (-3.5, 0) -> (-2, 0)
  line L5 (-3.5, -4) -> (-3.5, 0)
  line L6 (0, -4) -> (-3.5, -4)
  point P1 (0, 0)
  point P4 (0, 6)
  point P7 (0, -4)
  point P5 (-3.5, 0)
  point P6 (-3.5, -4)
  perpendicular L1 L2
  collinear P1 P4 P7
  perpendicular L1 L4
  coincident P1 L4
  vertical L1
  vertical L3
  parallel L3 L5
  coincident L3 P7
  perpendicular L3 L6
  dimension "d9" = 4 (= "adsk_nomdia")
  dimension "d66" = 7 (= "adsk_headdia")
  dimension "d68" distance P1 P4 = 6 (= "adsk_nomlen")
  dimension "d79" distance P5 P6 = 4 (= "adsk_headh")
revolve "Revolve1" sketch "Sketch1" AlongAngle 360
work_plane "WorkPlane1" AlongDistance 4 (= "adsk_headh")
sketch "Sketch6" plane through (0, 0, 4) normal (0, 0, 1) x axis (1, 0, 0)
  line L1 (1.5, 0) -> (-1.5, 0)
  line L2 (-1.5, 0.866) -> (0, 0)
  line L3 (-1.5, 0.866) -> (-1.5, -0.866)
  line L4 (0, 0) -> (-1.5, -0.866)
  point P1 (0, 0)
  point P4 (0, 0)
  point P2 (-1.5, 0)
  point P5 (-1.5, 0.866)
  point P7 (-1.5, 0.866)
  point P8 (0, 0)
  point P3 (1.5, 0)
  horizontal L1
  midpoint P1 L1
  coincident P1 P4
  perpendicular L1 L3
  midpoint P2 L3
  coincident P5 P7
  coincident P1 P8
  dimension "d72" distance P2 P3 = 3 (= "adsk_waflat")
  dimension "d100" angle L1 L2 = 150
extrude "Extrude1" cut sketch "Sketch6" profile of L2 L3 L4 no distance stored
circular_pattern "C-Pattern1" TotalAngle 360
extrude "Extrude2" cut of existing geometry no distance stored taper -85
thread "Thread2" ThreadOffset 0 ThreadLength 4.1706 (= "adsk_thrlen")
fillet "Fillet4" radius 0.4 (= "adsk_nomdia * 0.1")
sketch "Sketch7" plane through (0, 0, 0) normal (0, 1, 0) x axis (1, 0, 0)
  line L1 (-2.04, 5.5706) -> (-2.04, 6)
  line L2 (-1.5706, 6) -> (-2.04, 5.5706)
  line L3 (0, -4) -> (0, 6)
  line L4 (0, 6) -> (-2.04, 6)
  point P5 (0, 6)
  point P7 (0, 6)
  point P4 (-1.5706, 6)
  point P3 (-2.04, 5.5706)
  point P1 (0, 0)
  coincident P5 P7
  perpendicular L3 L4
  coincident P4 L4
  perpendicular L1 L4
  dimension "d92" distance P3 P4 = 0.4294 (= "adsk_startlen")
  dimension "d98" distance P1 P4 = 1.5706 (= "adsk_endpointdia / 2")
  dimension "d99" distance P1 L1 = 2.04 (= "adsk_nomdia * 0.51")
revolve "Revolve3" sketch "Sketch7" AlongAngle 360
joint_origin "JointOrigin2" OffsetX 0 OffsetY 0 OffsetZ 0 AngleZ 0

design "bolt"
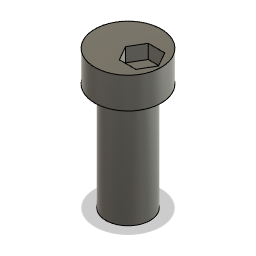
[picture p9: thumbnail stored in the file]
sketch "Sketch1" plane through (0, 0, 0) normal (0, 0, 1) x axis (1, 0, 0)
  line L1 (0, 12.5) -> (0, 0)
  line L2 (2, 0) -> (0, 0)
  line L3 (2, 9.6811) -> (2, 0)
  line L4 (3, 9.7) -> (0, 9.7)
  line L5 (3, 9.7) -> (2, 9.6811)
  line L6 (3, 12.5) -> (3, 9.7)
  line L7 (0, 12.5) -> (3, 12.5)
  line L8 (0, 12.5) -> (0, 0)
  point P1 (0, 0)
  point P2 (0, 0)
  point P4 (0, 0)
  point P7 (0, 9.7)
  point P10 (0, 0)
  point P3 (0, 12.5)
  point P5 (2, 0)
  point P8 (3, 9.7)
  point P9 (3, 12.5)
  coincident P1 P2
  vertical L1
  coincident P1 P4
  perpendicular L1 L2
  perpendicular L2 L3
  coincident L1 P7
  perpendicular L1 L4
  perpendicular L4 L6
  perpendicular L1 L7
  coincident P1 P10
  dimension "d2" distance P2 P3 = 12.5
  dimension "d3" distance P4 P5 = 2
  dimension "d5" distance P7 P8 = 3
  dimension "d7" distance P8 P9 = 2.8
revolve "Revolve1" sketch "Sketch1" AlongAngle 360
sketch "Sketch3" plane through (0, 12.5, 0) normal (0, 1, 0) x axis (-1, 0, 0)
  line L1 (-3, 0) -> (0, 0)
  line L2 (-0.5258, -1.3023) -> (-2.0257, -1.2957)
  line L3 (0.23, -0.0066) -> (-0.5258, -1.3023)
  line L4 (-0.5143, 1.2957) -> (0.23, -0.0066)
  line L5 (-2.0142, 1.3023) -> (-0.5143, 1.2957)
  line L6 (-2.77, 0.0066) -> (-2.0142, 1.3023)
  line L7 (-2.0257, -1.2957) -> (-2.77, 0.0066)
  circle C1 centre (0, 0) radius 3
  point P2 (0, 0)
  point P3 (0, 0)
  point P4 (-3, 0)
  point P11 (-1.27, 0)
  point P5 (-2.0257, -1.2957)
  coincident P2 P3
  coincident C1 P4
  horizontal L1
  coincident L1 P11
  dimension "d8" distance P5 P11 = 1.5
extrude "Extrude1" cut sketch "Sketch3" profile of L2 L3 L4 L5 L6 L7 against normal blind 1.27

design "Broached Hexagon Socket Head Cap Screw ANSI B18.3.1M - M5x0.8 x 20 Steel Grade 2 Plain"
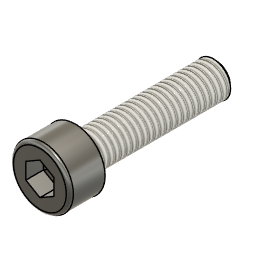
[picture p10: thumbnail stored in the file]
description: Broached Hexagon Socket Head Cap Screw ANSI B18.3.1M - M5x0.8 x 20
part number: arrangementsContainer
parameter "adsk_nomlen" = 20
parameter "adsk_headh" = 5
parameter "adsk_headdia" = 8.5
parameter "adsk_nomdia" = 5
parameter "adsk_waflat" = 4
parameter "adsk_keyend" = 2.5
parameter "adsk_thrlen" = 18.5185
parameter "adsk_startlen" = 0.4908
parameter "adsk_endpointdia" = 4.0185
sketch "Sketch1" plane through (0, 0, 0) normal (0, 1, 0) x axis (1, 0, 0)
  line L1 (-2.5, 20) -> (-2.5, 0)
  line L2 (0, 20) -> (-2.5, 20)
  line L3 (0, -5) -> (0, 20)
  line L4 (-4.25, 0) -> (-2.5, 0)
  line L5 (-4.25, -5) -> (-4.25, 0)
  line L6 (0, -5) -> (-4.25, -5)
  point P1 (0, 0)
  point P4 (0, 20)
  point P7 (0, -5)
  point P5 (-4.25, 0)
  point P6 (-4.25, -5)
  perpendicular L1 L2
  collinear P1 P4 P7
  perpendicular L1 L4
  coincident P1 L4
  vertical L1
  vertical L3
  parallel L3 L5
  coincident L3 P7
  perpendicular L3 L6
  dimension "d9" = 5 (= "adsk_nomdia")
  dimension "d66" = 8.5 (= "adsk_headdia")
  dimension "d68" distance P1 P4 = 20 (= "adsk_nomlen")
  dimension "d79" distance P5 P6 = 5 (= "adsk_headh")
revolve "Revolve1" sketch "Sketch1" AlongAngle 360
work_plane "WorkPlane1" AlongDistance 5 (= "adsk_headh")
sketch "Sketch6" plane through (0, 0, 5) normal (0, 0, 1) x axis (1, 0, 0)
  line L1 (2, 0) -> (-2, 0)
  line L2 (-2, 1.1547) -> (0, 0)
  line L3 (-2, 1.1547) -> (-2, -1.1547)
  line L4 (0, 0) -> (-2, -1.1547)
  point P1 (0, 0)
  point P4 (0, 0)
  point P2 (-2, 0)
  point P5 (-2, 1.1547)
  point P7 (-2, 1.1547)
  point P8 (0, 0)
  point P3 (2, 0)
  horizontal L1
  midpoint P1 L1
  coincident P1 P4
  perpendicular L1 L3
  midpoint P2 L3
  coincident P5 P7
  coincident P1 P8
  dimension "d72" distance P2 P3 = 4 (= "adsk_waflat")
  dimension "d100" angle L1 L2 = 150
extrude "Extrude1" cut sketch "Sketch6" profile of L2 L3 L4 no distance stored
circular_pattern "C-Pattern1" TotalAngle 360
extrude "Extrude2" cut of existing geometry no distance stored taper -85
thread "Thread2" ThreadOffset 0 ThreadLength 18.5185 (= "adsk_thrlen")
fillet "Fillet4" radius 0.5 (= "adsk_nomdia * 0.1")
sketch "Sketch7" plane through (0, 0, 0) normal (0, 1, 0) x axis (1, 0, 0)
  line L1 (-2.55, 19.5092) -> (-2.55, 20)
  line L2 (-2.0092, 20) -> (-2.55, 19.5092)
  line L3 (0, -5) -> (0, 20)
  line L4 (0, 20) -> (-2.55, 20)
  point P5 (0, 20)
  point P7 (0, 20)
  point P4 (-2.0092, 20)
  point P3 (-2.55, 19.5092)
  point P1 (0, 0)
  coincident P5 P7
  perpendicular L3 L4
  coincident P4 L4
  perpendicular L1 L4
  dimension "d92" distance P3 P4 = 0.4908 (= "adsk_startlen")
  dimension "d98" distance P1 P4 = 2.0092 (= "adsk_endpointdia / 2")
  dimension "d99" distance P1 L1 = 2.55 (= "adsk_nomdia * 0.51")
revolve "Revolve3" sketch "Sketch7" AlongAngle 360
joint_origin "JointOrigin2" OffsetX 0 OffsetY 0 OffsetZ 0 AngleZ 0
